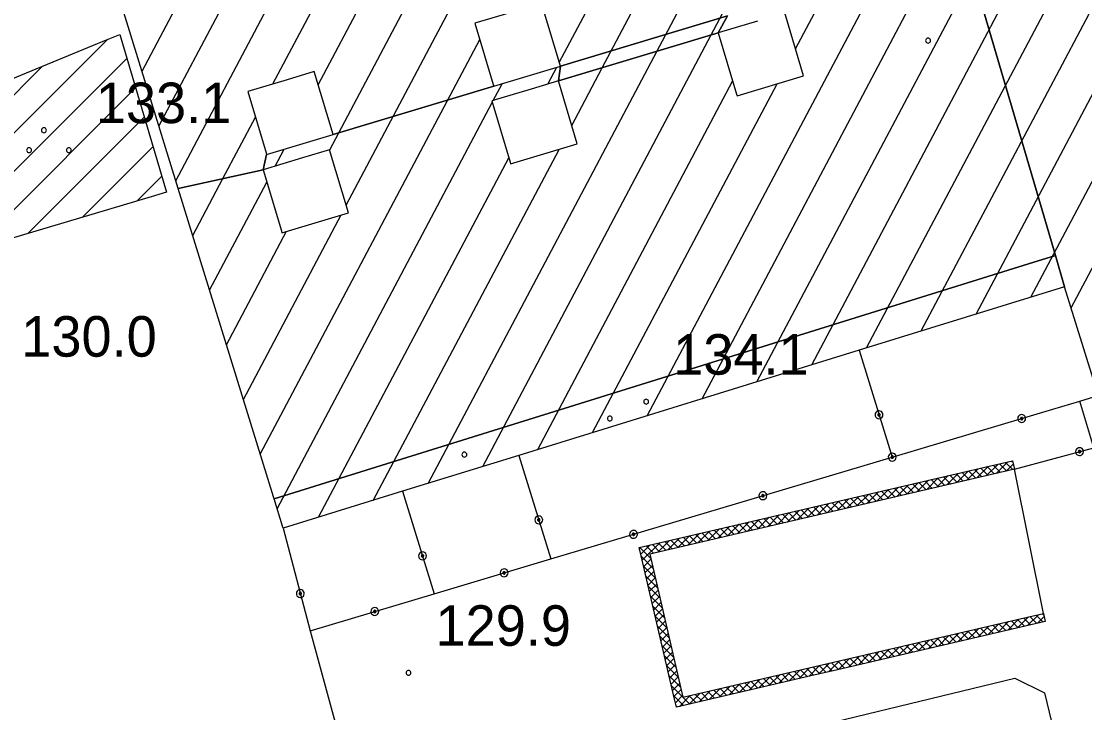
# Model space of a CAD drawing. Extents: x 513373 to 514978, y 5038576 to 5040180.
# Drawn here: x 513585.9 to 513625.28, y 5038637.54 to 5038663.13 of the extents above; entities that cross this region are included whole.
import ezdxf

# ---------------------------------------------------------------- set-up
doc = ezdxf.new("R2010")
doc.units = 0
for name, color, linetype in [('3010204', 7, 'Continuous'), ('3090300', 7, 'Continuous'), ('C1131', 7, 'Continuous'), ('C12211', 7, 'Continuous'), ('C21195', 7, 'Continuous'), ('C2911', 7, 'Continuous'), ('C2912', 7, 'Continuous'), ('C4114', 7, 'Continuous'), ('CAMP_C12211', 7, 'Continuous'), ('CAMP_C21195', 7, 'Continuous'), ('CAMP_C4114', 7, 'Continuous'), ('Default', 7, 'Continuous'), ('F12107', 7, 'Continuous'), ('F12131', 7, 'Continuous'), ('F12132', 7, 'Continuous'), ('TOP920', 7, 'Continuous')]:
    doc.layers.add(name, color=color, linetype=linetype)

# ---------------------------------------------------------------- blocks, each defined once
blk = doc.blocks.new('CAMP_13884420')
at = {"layer": 'CAMP_C12211'}
for p, q in [((3.759, -1.025), (15.346, 20.859)), ((-1.731, -14.6), (15.962, 18.817)), ((0.298, -13.973), (16.578, 16.775)), ((2.327, -13.346), (17.194, 14.733)), ((4.356, -12.719), (17.811, 12.691)), ((-3.398, -1.719), (4.036, 12.321)), ((-4.99, -1.52), (2.007, 11.694)), ((6.386, -12.092), (18.427, 10.65)), ((-12.88, -6.805), (-4.081, 9.812)), ((-13.494, -4.76), (-6.11, 9.185)), ((-13.916, -2.351), (-8.14, 8.558)), ((8.415, -11.465), (19.043, 8.608)), ((-15.597, -2.321), (-10.169, 7.931)), ((-19.19, -5.901), (-12.198, 7.304)), ((-19.815, -3.877), (-14.228, 6.677)), ((10.444, -10.838), (19.659, 6.566)), ((-20.441, -1.852), (-16.257, 6.05)), ((12.474, -10.211), (20.276, 4.524)), ((-1.379, -1.113), (0.542, 2.515)), ((13.962, -10.605), (20.892, 2.482)), ((0.639, -0.506), (1.156, 0.47)), ((-16.063, -16.022), (-7.934, -0.671)), ((-7.819, -16.481), (0.639, -0.506)), ((-9.849, -17.109), (-1.379, -1.113)), ((-5.416, -2.326), (-5.086, -1.702)), ((-4.529, -3.857), (-3.398, -1.719)), ((-7.435, -2.933), (-7.104, -2.309)), ((-5.79, -15.854), (1.428, -2.221)), ((-3.761, -15.227), (3.076, -2.314)), ((-15.437, -18.047), (-7.474, -3.007)), ((-17.452, -5.824), (-16.246, -3.547)), ((-15.509, -5.36), (-15.178, -4.735)), ((-13.907, -18.363), (-6.86, -5.053)), ((-11.878, -17.736), (-4.998, -4.741)), ((-18.564, -7.925), (-17.452, -5.824)), ((-17.939, -9.949), (-15.824, -5.955)), ((-16.688, -13.998), (-13.072, -7.168)), ((-17.314, -11.974), (-15.09, -7.775))]:
    blk.add_line(p, q, dxfattribs=at)
blk = doc.blocks.new('CAMP_1860F2A3')
at = {"layer": 'CAMP_C21195'}
for p, q in [((-3.757, -1.636), (1.994, 4.115)), ((-3.276, -2.569), (2.71, 3.417)), ((-4.239, -0.703), (-0.411, 3.125)), ((-4.72, 0.23), (-2.816, 2.134)), ((-2.795, -3.502), (3.034, 2.327)), ((-0.937, -3.059), (3.358, 1.237)), ((1.076, -2.459), (3.682, 0.146)), ((3.09, -1.86), (4.006, -0.944))]:
    blk.add_line(p, q, dxfattribs=at)
blk = doc.blocks.new('CAMP_9A74330B')
at = {"layer": 'CAMP_C4114'}
for p, q in [((6.674, 4.319), (7.108, 4.753)), ((7.291, 4.462), (7.021, 4.733)), ((7.282, 4.754), (7.25, 4.786)), ((5.2, 3.976), (5.635, 4.411)), ((5.685, 4.089), (5.414, 4.36)), ((5.568, 4.062), (6.003, 4.497)), ((5.914, 4.142), (5.643, 4.413)), ((6.144, 4.196), (5.873, 4.467)), ((5.937, 4.148), (6.372, 4.582)), ((6.373, 4.249), (6.102, 4.52)), ((6.305, 4.233), (6.74, 4.668)), ((6.603, 4.302), (6.332, 4.573)), ((6.832, 4.356), (6.561, 4.626)), ((7.062, 4.409), (6.791, 4.68)), ((7.042, 4.404), (7.303, 4.665)), ((3.358, 3.549), (3.792, 3.983)), ((3.726, 3.634), (4.161, 4.069)), ((4.078, 3.716), (3.807, 3.987)), ((4.307, 3.769), (4.037, 4.04)), ((4.095, 3.72), (4.529, 4.154)), ((4.537, 3.822), (4.266, 4.093)), ((4.463, 3.805), (4.898, 4.24)), ((4.766, 3.876), (4.496, 4.147)), ((4.996, 3.929), (4.725, 4.2)), ((4.832, 3.891), (5.266, 4.326)), ((5.226, 3.982), (4.955, 4.253)), ((5.455, 4.036), (5.184, 4.307)), ((1.516, 3.121), (1.95, 3.555)), ((1.884, 3.206), (2.319, 3.641)), ((2.242, 3.289), (1.971, 3.56)), ((2.471, 3.343), (2.201, 3.613)), ((2.253, 3.292), (2.687, 3.726)), ((2.701, 3.396), (2.43, 3.666)), ((2.621, 3.377), (3.055, 3.812)), ((2.93, 3.449), (2.66, 3.72)), ((3.16, 3.502), (2.889, 3.773)), ((2.989, 3.463), (3.424, 3.897)), ((3.389, 3.556), (3.119, 3.826)), ((3.619, 3.609), (3.348, 3.88)), ((3.848, 3.662), (3.578, 3.933)), ((0.042, 2.778), (0.476, 3.212)), ((0.635, 2.916), (0.365, 3.186)), ((0.41, 2.864), (0.845, 3.298)), ((0.865, 2.969), (0.594, 3.24)), ((0.779, 2.949), (1.213, 3.384)), ((1.094, 3.023), (0.824, 3.293)), ((1.324, 3.076), (1.053, 3.346)), ((1.147, 3.035), (1.582, 3.469)), ((1.553, 3.129), (1.283, 3.4)), ((1.783, 3.183), (1.512, 3.453)), ((2.012, 3.236), (1.742, 3.506)), ((-1.8, 2.35), (-1.366, 2.784)), ((-1.201, 2.489), (-1.471, 2.76)), ((-1.432, 2.436), (-0.998, 2.87)), ((-0.972, 2.543), (-1.242, 2.813)), ((-1.063, 2.521), (-0.629, 2.955)), ((-0.742, 2.596), (-1.012, 2.866)), ((-0.513, 2.649), (-0.783, 2.92)), ((-0.695, 2.607), (-0.261, 3.041)), ((-0.283, 2.703), (-0.553, 2.973)), ((-0.327, 2.693), (0.108, 3.127)), ((-0.053, 2.756), (-0.324, 3.026)), ((0.176, 2.809), (-0.094, 3.08)), ((0.406, 2.863), (0.135, 3.133)), ((-3.274, 2.008), (-2.84, 2.442)), ((-2.808, 2.116), (-3.078, 2.386)), ((-2.906, 2.093), (-2.472, 2.527)), ((-2.578, 2.169), (-2.848, 2.44)), ((-2.349, 2.223), (-2.619, 2.493)), ((-2.537, 2.179), (-2.103, 2.613)), ((-2.119, 2.276), (-2.389, 2.546)), ((-2.169, 2.265), (-1.735, 2.698)), ((-1.89, 2.329), (-2.16, 2.6)), ((-1.66, 2.383), (-1.93, 2.653)), ((-1.431, 2.436), (-1.701, 2.706)), ((-5.116, 1.58), (-4.683, 2.013)), ((-4.748, 1.665), (-4.314, 2.099)), ((-4.414, 1.743), (-4.684, 2.013)), ((-4.185, 1.796), (-4.455, 2.066)), ((-4.379, 1.751), (-3.946, 2.185)), ((-3.955, 1.85), (-4.225, 2.12)), ((-4.011, 1.837), (-3.577, 2.27)), ((-3.726, 1.903), (-3.996, 2.173)), ((-3.496, 1.956), (-3.766, 2.226)), ((-3.642, 1.922), (-3.209, 2.356)), ((-3.267, 2.009), (-3.537, 2.28)), ((-3.037, 2.063), (-3.307, 2.333)), ((-6.542, 1.569), (-6.525, 1.585)), ((-6.124, 1.19), (-6.52, 1.586)), ((-6.488, 1.339), (-6.157, 1.671)), ((-6.435, 1.11), (-5.788, 1.756)), ((-6.021, 1.37), (-6.291, 1.64)), ((-5.791, 1.423), (-6.061, 1.693)), ((-5.853, 1.409), (-5.42, 1.842)), ((-5.562, 1.476), (-5.832, 1.746)), ((-5.332, 1.53), (-5.602, 1.8)), ((-5.485, 1.494), (-5.051, 1.928)), ((-5.103, 1.583), (-5.373, 1.853)), ((-4.873, 1.636), (-5.143, 1.906)), ((-4.644, 1.69), (-4.914, 1.96)), ((-6.038, 0.821), (-6.468, 1.251)), ((-6.382, 0.88), (-6.114, 1.148)), ((-5.953, 0.453), (-6.382, 0.882)), ((-6.328, 0.651), (-6.061, 0.918)), ((-5.867, 0.084), (-6.297, 0.514)), ((-6.275, 0.421), (-6.008, 0.688)), ((-6.222, 0.192), (-5.954, 0.459)), ((-5.782, -0.284), (-6.211, 0.145)), ((-6.168, -0.038), (-5.901, 0.229)), ((-6.115, -0.268), (-5.848, 0)), ((-5.696, -0.652), (-6.125, -0.223)), ((-6.062, -0.497), (-5.794, -0.23)), ((-5.61, -1.021), (-6.04, -0.591)), ((-6.008, -0.727), (-5.741, -0.459)), ((-5.955, -0.956), (-5.688, -0.689)), ((-5.525, -1.389), (-5.954, -0.96)), ((-5.902, -1.186), (-5.634, -0.918)), ((-5.849, -1.415), (-5.581, -1.148)), ((6.729, -1.566), (7.133, -1.162)), ((7.097, -1.48), (7.501, -1.077)), ((7.486, -1.39), (7.235, -1.138)), ((7.716, -1.336), (7.464, -1.085)), ((7.466, -1.395), (7.869, -0.992)), ((7.945, -1.283), (7.694, -1.032)), ((7.834, -1.309), (8.237, -0.907)), ((8.175, -1.23), (7.924, -0.979)), ((8.405, -1.177), (8.154, -0.926)), ((8.203, -1.223), (8.449, -0.977)), ((8.437, -0.926), (8.383, -0.873)), ((-5.439, -1.758), (-5.869, -1.328)), ((-5.795, -1.645), (-5.528, -1.377)), ((5.255, -1.908), (5.659, -1.505)), ((5.65, -1.816), (5.399, -1.565)), ((5.624, -1.822), (6.027, -1.419)), ((5.88, -1.763), (5.628, -1.512)), ((6.109, -1.71), (5.858, -1.458)), ((5.992, -1.737), (6.396, -1.333)), ((6.339, -1.656), (6.087, -1.405)), ((6.568, -1.603), (6.317, -1.352)), ((6.36, -1.651), (6.764, -1.248)), ((6.798, -1.55), (6.546, -1.298)), ((7.027, -1.496), (6.776, -1.245)), ((7.257, -1.443), (7.005, -1.192)), ((-5.354, -2.126), (-5.783, -1.697)), ((-5.742, -1.874), (-5.474, -1.607)), ((-5.689, -2.104), (-5.421, -1.836)), ((3.413, -2.336), (3.817, -1.933)), ((3.782, -2.25), (4.185, -1.847)), ((4.043, -2.19), (3.792, -1.938)), ((4.273, -2.136), (4.022, -1.885)), ((4.15, -2.165), (4.553, -1.761)), ((4.503, -2.083), (4.251, -1.832)), ((4.732, -2.03), (4.481, -1.778)), ((4.518, -2.079), (4.922, -1.676)), ((4.962, -1.976), (4.71, -1.725)), ((4.887, -1.994), (5.29, -1.59)), ((5.191, -1.923), (4.94, -1.672)), ((5.421, -1.87), (5.169, -1.618)), ((-5.268, -2.495), (-5.698, -2.065)), ((-5.635, -2.333), (-5.368, -2.066)), ((-5.582, -2.563), (-5.314, -2.295)), ((1.571, -2.764), (1.974, -2.361)), ((1.939, -2.678), (2.343, -2.275)), ((2.437, -2.563), (2.186, -2.311)), ((2.308, -2.593), (2.711, -2.189)), ((2.666, -2.509), (2.415, -2.258)), ((2.896, -2.456), (2.645, -2.205)), ((2.676, -2.507), (3.08, -2.104)), ((3.125, -2.403), (2.874, -2.152)), ((3.045, -2.422), (3.448, -2.018)), ((3.355, -2.349), (3.104, -2.098)), ((3.584, -2.296), (3.333, -2.045)), ((3.814, -2.243), (3.563, -1.992)), ((-5.182, -2.863), (-5.612, -2.434)), ((-5.529, -2.792), (-5.261, -2.525)), ((-5.475, -3.022), (-5.208, -2.754)), ((0.097, -3.106), (0.5, -2.703)), ((0.601, -2.989), (0.349, -2.738)), ((0.466, -3.021), (0.869, -2.617)), ((0.83, -2.936), (0.579, -2.685)), ((1.06, -2.883), (0.808, -2.631)), ((0.834, -2.935), (1.237, -2.532)), ((1.289, -2.829), (1.038, -2.578)), ((1.203, -2.849), (1.606, -2.446)), ((1.519, -2.776), (1.268, -2.525)), ((1.748, -2.723), (1.497, -2.471)), ((1.978, -2.669), (1.727, -2.418)), ((2.207, -2.616), (1.956, -2.365)), ((-5.097, -3.231), (-5.526, -2.802)), ((-5.422, -3.251), (-5.154, -2.984)), ((-1.745, -3.534), (-1.342, -3.131)), ((-1.376, -3.448), (-0.973, -3.045)), ((-1.006, -3.362), (-1.257, -3.111)), ((-0.777, -3.309), (-1.028, -3.058)), ((-1.008, -3.363), (-0.605, -2.96)), ((-0.547, -3.256), (-0.798, -3.005)), ((-0.639, -3.277), (-0.236, -2.874)), ((-0.318, -3.202), (-0.569, -2.951)), ((-0.088, -3.149), (-0.339, -2.898)), ((-0.271, -3.192), (0.132, -2.789)), ((0.142, -3.096), (-0.11, -2.845)), ((0.371, -3.043), (0.12, -2.791)), ((-5.011, -3.6), (-5.441, -3.17)), ((-5.369, -3.481), (-5.101, -3.213)), ((-4.679, -4.215), (-5.355, -3.539)), ((-5.315, -3.711), (-5.048, -3.443)), ((-3.218, -3.876), (-2.816, -3.473)), ((-2.843, -3.789), (-3.093, -3.538)), ((-2.613, -3.735), (-2.864, -3.485)), ((-2.85, -3.79), (-2.447, -3.388)), ((-2.383, -3.682), (-2.634, -3.431)), ((-2.481, -3.705), (-2.079, -3.302)), ((-2.154, -3.629), (-2.405, -3.378)), ((-1.924, -3.576), (-2.175, -3.325)), ((-2.113, -3.619), (-1.71, -3.217)), ((-1.695, -3.522), (-1.946, -3.271)), ((-1.465, -3.469), (-1.716, -3.218)), ((-1.236, -3.416), (-1.487, -3.165)), ((-4.908, -4.268), (-5.27, -3.907)), ((-5.262, -3.94), (-4.994, -3.672)), ((-5.209, -4.17), (-4.941, -3.902)), ((-5.06, -4.304), (-4.658, -3.902)), ((-4.449, -4.162), (-4.7, -3.911)), ((-4.692, -4.218), (-4.289, -3.816)), ((-4.22, -4.109), (-4.47, -3.858)), ((-4.323, -4.133), (-3.921, -3.73)), ((-3.99, -4.055), (-4.241, -3.805)), ((-3.761, -4.002), (-4.011, -3.751)), ((-3.955, -4.047), (-3.553, -3.645)), ((-3.531, -3.949), (-3.782, -3.698)), ((-3.586, -3.962), (-3.184, -3.559)), ((-3.302, -3.895), (-3.552, -3.645)), ((-3.072, -3.842), (-3.323, -3.591)), ((-5.138, -4.322), (-5.184, -4.276))]:
    blk.add_line(p, q, dxfattribs=at)
blk = doc.blocks.new('03080200')
at = {"layer": 'Default'}
for p, q in [((-0.139, 0.046), (-0.146, 0)), ((-0.146, 0), (-0.139, -0.046)), ((-0.118, 0.086), (-0.139, 0.046)), ((-0.086, 0.118), (-0.118, 0.086)), ((-0.046, 0.139), (-0.086, 0.118)), ((0, 0.146), (-0.046, 0.139)), ((-0.042, 0.014), (-0.045, 0)), ((-0.045, 0), (-0.042, -0.014)), ((-0.036, 0.026), (-0.042, 0.014)), ((-0.026, 0.036), (-0.036, 0.026)), ((-0.014, 0.042), (-0.026, 0.036)), ((0, 0.045), (-0.014, 0.042)), ((0.046, 0.139), (0, 0.146)), ((0.014, 0.042), (0, 0.045)), ((0.026, 0.036), (0.014, 0.042)), ((0.036, 0.026), (0.026, 0.036)), ((0.042, 0.014), (0.036, 0.026)), ((0.045, 0), (0.042, 0.014)), ((0.042, -0.014), (0.045, 0)), ((0.086, 0.118), (0.046, 0.139)), ((0.118, 0.086), (0.086, 0.118)), ((0.139, 0.046), (0.118, 0.086)), ((0.146, 0), (0.139, 0.046)), ((0.139, -0.046), (0.146, 0)), ((-0.139, -0.046), (-0.118, -0.086)), ((-0.118, -0.086), (-0.086, -0.118)), ((-0.086, -0.118), (-0.046, -0.139)), ((-0.046, -0.139), (0, -0.146)), ((-0.042, -0.014), (-0.036, -0.026)), ((-0.036, -0.026), (-0.026, -0.036)), ((-0.026, -0.036), (-0.014, -0.042)), ((-0.014, -0.042), (0, -0.045)), ((0, -0.045), (0.014, -0.042)), ((0, -0.146), (0.046, -0.139)), ((0.014, -0.042), (0.026, -0.036)), ((0.026, -0.036), (0.036, -0.026)), ((0.036, -0.026), (0.042, -0.014)), ((0.046, -0.139), (0.086, -0.118)), ((0.086, -0.118), (0.118, -0.086)), ((0.118, -0.086), (0.139, -0.046))]:
    blk.add_line(p, q, dxfattribs=at)
blk = doc.blocks.new('08020400')
at = {"layer": 'Default'}
for p, q in [((-0.086, 0.028), (-0.09, 0)), ((-0.09, 0), (-0.086, -0.028)), ((-0.073, 0.053), (-0.086, 0.028)), ((-0.053, 0.073), (-0.073, 0.053)), ((-0.028, 0.086), (-0.053, 0.073)), ((0, 0.09), (-0.028, 0.086)), ((0.028, 0.086), (0, 0.09)), ((0.053, 0.073), (0.028, 0.086)), ((0.073, 0.053), (0.053, 0.073)), ((0.086, 0.028), (0.073, 0.053)), ((0.09, 0), (0.086, 0.028)), ((0.086, -0.028), (0.09, 0)), ((-0.086, -0.028), (-0.073, -0.053)), ((-0.073, -0.053), (-0.053, -0.073)), ((-0.053, -0.073), (-0.028, -0.086)), ((-0.028, -0.086), (0, -0.09)), ((0, -0.09), (0.028, -0.086)), ((0.028, -0.086), (0.053, -0.073)), ((0.053, -0.073), (0.073, -0.053)), ((0.073, -0.053), (0.086, -0.028))]:
    blk.add_line(p, q, dxfattribs=at)
blk = doc.blocks.new('NSIMB25')
at = {"layer": 'Default'}
for p, q in [((-0.086, 0.028), (-0.09, 0)), ((-0.09, 0), (-0.086, -0.028)), ((-0.073, 0.053), (-0.086, 0.028)), ((-0.053, 0.073), (-0.073, 0.053)), ((-0.028, 0.086), (-0.053, 0.073)), ((0, 0.09), (-0.028, 0.086)), ((0.028, 0.086), (0, 0.09)), ((0.053, 0.073), (0.028, 0.086)), ((0.073, 0.053), (0.053, 0.073)), ((0.086, 0.028), (0.073, 0.053)), ((0.09, 0), (0.086, 0.028)), ((0.086, -0.028), (0.09, 0)), ((-0.086, -0.028), (-0.073, -0.053)), ((-0.073, -0.053), (-0.053, -0.073)), ((-0.053, -0.073), (-0.028, -0.086)), ((-0.028, -0.086), (0, -0.09)), ((0, -0.09), (0.028, -0.086)), ((0.028, -0.086), (0.053, -0.073)), ((0.053, -0.073), (0.073, -0.053)), ((0.073, -0.053), (0.086, -0.028))]:
    blk.add_line(p, q, dxfattribs=at)
blk = doc.blocks.new('A$C3704598A')
at = {"layer": '3010204'}
blk.add_lwpolyline([(243.479, -750.179), (242.993, -749.64), (242.406, -749.213), (241.743, -748.918), (241.034, -748.767), (239.861, -743.689), (249.651, -741.327), (250.751, -741.869), (252.207, -747.899), (245.095, -749.757), (244.033, -750.035), (243.479, -750.179)], dxfattribs=at)
at = {"layer": '3090300'}
blk.add_lwpolyline([(250.71, -738.932), (249.635, -733.593)], dxfattribs=at)
at = {"layer": 'C1131'}
for points in [[(253.285, -730.7), (252.739, -730.865), (252.718, -730.797), (251.493, -726.833), (251.152, -725.672), (247.781, -714.213), (248.265, -714.071), (245.205, -703.637), (244.029, -699.829), (243.87, -699.317), (242.358, -694.422), (250.722, -691.837), (251.724, -691.528), (253.122, -696.162), (253.143, -696.229), (253.412, -697.122), (257.134, -709.456), (257.16, -709.544), (257.615, -711.051), (262.688, -727.862), (259.089, -728.949), (258.083, -729.252)], [(218.234, -723.332), (217.669, -723.5), (211.307, -725.394), (211.277, -725.335), (209.482, -721.855), (208.857, -720.644), (215.526, -717.896), (215.891, -717.746), (216.501, -717.495)], [(251.493, -726.833), (250.493, -727.142), (243.882, -729.185), (231.283, -733.077), (226.977, -734.408), (222.557, -735.774), (222.535, -735.701), (222.22, -734.683), (250.151, -725.983), (251.152, -725.672)], [(259.656, -731.147), (252.576, -732.796), (252.575, -732.793), (252.056, -731.071), (252.739, -730.865), (253.285, -730.7), (258.083, -729.252), (259.089, -728.949)]]:
    blk.add_lwpolyline(points, close=True, dxfattribs=at)
for points in [[(240.126, -716.998), (238.662, -717.437), (239.009, -716.808)], [(239.009, -716.808), (232.824, -718.667), (232.124, -716.337)], [(231.121, -716.639), (229.657, -717.078), (230.338, -719.343), (230.357, -719.409), (224.408, -721.197), (223.708, -718.867), (222.705, -719.169), (221.241, -719.608), (221.922, -721.873), (221.941, -721.938), (221.809, -722.503), (222.491, -724.768), (222.51, -724.833), (224.976, -724.092), (224.276, -721.762), (223.273, -722.064), (221.809, -722.503), (218.67, -723.194), (215.467, -712.826)], [(247.781, -714.213), (251.152, -725.672), (250.151, -725.983), (222.22, -734.683), (222.197, -734.608), (218.67, -723.194), (221.809, -722.503), (221.941, -721.938), (224.408, -721.197), (230.357, -719.409), (232.824, -718.667), (232.747, -719.215), (231.744, -719.517), (230.28, -719.957), (230.961, -722.222), (230.98, -722.287), (233.447, -721.546), (232.747, -719.215), (232.824, -718.667), (239.009, -716.808), (238.662, -717.437), (239.343, -719.702), (239.362, -719.768), (241.829, -719.027), (241.129, -716.696)]]:
    blk.add_lwpolyline(points, dxfattribs=at)
at = {"layer": 'C12211'}
for points in [[(252.718, -730.797), (251.493, -726.833), (250.493, -727.142), (243.882, -729.185), (231.283, -733.077), (226.977, -734.408), (222.557, -735.774), (222.535, -735.701), (222.22, -734.683), (222.197, -734.608), (218.67, -723.194), (221.809, -722.503), (221.941, -721.938), (224.408, -721.197), (223.708, -718.867), (222.705, -719.169), (221.241, -719.608), (221.922, -721.873), (221.941, -721.938), (221.809, -722.503), (222.491, -724.768), (222.51, -724.833), (224.976, -724.092), (224.276, -721.762), (223.273, -722.064), (221.809, -722.503), (218.67, -723.194), (215.467, -712.826)], [(239.009, -716.808), (238.662, -717.437), (232.747, -719.215), (232.824, -718.667), (232.124, -716.337)], [(231.121, -716.639), (229.657, -717.078), (230.338, -719.343), (230.357, -719.409), (232.824, -718.667), (232.747, -719.215), (231.744, -719.517), (230.28, -719.957), (230.961, -722.222), (230.98, -722.287), (233.447, -721.546), (232.747, -719.215), (238.662, -717.437), (239.343, -719.702), (239.362, -719.768), (241.829, -719.027), (241.129, -716.696)], [(240.126, -716.998), (238.662, -717.437), (239.009, -716.808)]]:
    blk.add_lwpolyline(points, dxfattribs=at)
at = {"layer": 'C21195'}
for points in [[(218.234, -723.332), (217.669, -723.5), (211.307, -725.394), (211.277, -725.335), (209.482, -721.855), (208.857, -720.644), (215.526, -717.896), (215.891, -717.746), (216.501, -717.495)], [(259.656, -731.147), (252.576, -732.796), (252.575, -732.793), (252.056, -731.071), (252.739, -730.865), (253.285, -730.7), (258.083, -729.252), (259.089, -728.949)]]:
    blk.add_lwpolyline(points, close=True, dxfattribs=at)
at = {"layer": 'C2911'}
for points in [[(243.882, -729.185), (245.104, -733.144)], [(223.55, -739.57), (228.149, -738.198), (232.468, -736.911), (245.104, -733.144), (251.052, -731.37), (252.056, -731.071)], [(249.635, -733.593), (252.576, -732.796)], [(231.283, -733.077), (232.468, -736.911)], [(226.977, -734.408), (228.149, -738.198)]]:
    blk.add_lwpolyline(points, dxfattribs=at)
at = {"layer": 'C2912'}
blk.add_lwpolyline([(222.557, -735.774), (223.55, -739.57), (230.759, -766.01), (230.763, -766.025)], dxfattribs=at)
at = {"layer": 'C4114'}
blk.add_lwpolyline([(249.635, -733.593), (236.129, -736.73), (237.361, -742.032), (249.687, -739.168), (250.71, -738.932), (250.778, -739.225), (243.081, -741.012), (242.095, -741.241), (237.116, -742.398), (237.048, -742.104), (235.816, -736.801), (235.743, -736.487), (248.538, -733.514), (249.561, -733.277)], close=True, dxfattribs=at)
at = {"layer": 'C2911'}
for p, rotation in [((244.62, -731.573), -72.84725148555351), ((249.904, -731.712), 16.60311124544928), ((252.048, -732.939), 15.161940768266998), ((245.112, -733.141), 16.60311124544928), ((240.321, -734.57), 16.603535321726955), ((232.021, -735.466), -72.82565545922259), ((235.529, -735.999), 16.603535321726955), ((227.716, -736.797), -72.8173849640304), ((230.738, -737.427), 16.59248566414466), ((225.946, -738.856), 16.610380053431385)]:
    blk.add_blockref('03080200', p, dxfattribs=dict(at, rotation=rotation))
at = {"layer": 'C2912', "rotation": -75.34122349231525}
blk.add_blockref('03080200', (223.19, -738.193), dxfattribs=at)
at = {"layer": 'CAMP_C12211'}
blk.add_blockref('CAMP_13884420', (237.772, -717.007), dxfattribs=at)
at = {"layer": 'CAMP_C21195'}
blk.add_blockref('CAMP_1860F2A3', (214.053, -721.797), dxfattribs=at)
at = {"layer": 'CAMP_C4114'}
blk.add_blockref('CAMP_9A74330B', (242.288, -738.068), dxfattribs=at)
at = {"layer": 'F12107'}
for p in [(246.438, -717.723), (214.616, -721.777), (235.997, -731.089), (227.195, -741.127)]:
    blk.add_blockref('08020400', p, dxfattribs=at)
at = {"layer": 'F12131'}
for p in [(213.145, -721.777), (229.265, -733.05)]:
    blk.add_blockref('NSIMB25', p, dxfattribs=at)
at = {"layer": 'F12132'}
for p in [(213.696, -721.042), (234.652, -731.71)]:
    blk.add_blockref('NSIMB25', p, dxfattribs=at)
at = {"layer": 'TOP920'}
for s, p in [('133.1', (215.616, -720.777)), ('130.0', (212.856, -729.422)), ('134.1', (236.997, -730.089)), ('129.9', (228.195, -740.127))]:
    blk.add_text(s, height=1.5, dxfattribs=at).set_placement(p)

msp = doc.modelspace()

# ---------------------------------------------------------------- block references
at = {"layer": 'Default'}
msp.add_blockref('A$C3704598A', (513373.046, 5039380.14), dxfattribs=at)

doc.saveas('drawing.dxf')
